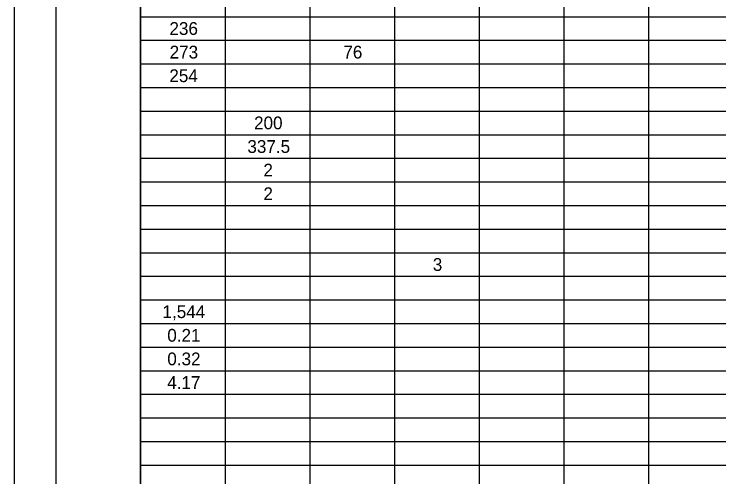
# Model space of a CAD drawing. Extents: x 0 to 34, y 0 to 22.
# Drawn here: x 0 to 8.36, y 11 to 16.49 of the extents above; entities that cross this region are included whole.
import ezdxf

# ---------------------------------------------------------------- set-up
doc = ezdxf.new("R2010")
doc.units = 0
for name, color, linetype in [('Default', 7, 'Continuous'), ('SH_Border', 7, 'Continuous'), ('SH_Cut_Line', 7, 'Continuous')]:
    doc.layers.add(name, color=color, linetype=linetype)

msp = doc.modelspace()

# ---------------------------------------------------------------- linework, layer by layer
at = {"layer": 'Default'}
for p, q in [((1.5, 21.5), (1.5, 0.5)), ((2.5046, 20.94), (2.5046, 0.5)), ((3.5092, 20.94), (3.5092, 0.5)), ((4.5138, 20.94), (4.5138, 0.5)), ((5.5184, 20.94), (5.5184, 0.5)), ((6.5229, 20.94), (6.5229, 0.5)), ((7.5275, 20.94), (7.5275, 0.5)), ((1.5, 16.46), (32, 16.46)), ((1.5, 16.18), (32, 16.18)), ((1.5, 15.9), (32, 15.9)), ((1.5, 15.62), (32, 15.62)), ((1.5, 15.34), (32, 15.34)), ((1.5, 15.06), (32, 15.06)), ((1.5, 14.78), (32, 14.78)), ((1.5, 14.5), (32, 14.5)), ((1.5, 14.22), (32, 14.22)), ((1.5, 13.94), (32, 13.94)), ((1.5, 13.66), (32, 13.66)), ((1.5, 13.38), (32, 13.38)), ((1.5, 13.1), (32, 13.1)), ((1.5, 12.82), (32, 12.82)), ((1.5, 12.54), (32, 12.54)), ((1.5, 12.26), (32, 12.26)), ((1.5, 11.98), (32, 11.98)), ((1.5, 11.7), (32, 11.7)), ((1.5, 11.42), (32, 11.42)), ((1.5, 11.14), (32, 11.14))]:
    msp.add_line(p, q, dxfattribs=at)
at = {"layer": 'SH_Border'}
for points in [[(0.5, 21.5), (1.5, 21.5), (1.5, 0.5), (0.5, 0.5)], [(1.5, 21.5), (33.5, 21.5), (33.5, 0.5), (1.5, 0.5)]]:
    msp.add_lwpolyline(points, close=True, dxfattribs=at)
at = {"layer": 'SH_Cut_Line'}
msp.add_lwpolyline([(0, 0), (34, 0), (34, 22), (0, 22)], close=True, dxfattribs=at)

# ---------------------------------------------------------------- texts
at = {"layer": 'Default'}
for s, height, p in [('236', 0.15153, (1.8433, 16.2442)), ('273', 0.15153, (1.8456, 15.9642)), ('76', 0.15153, (3.9069, 15.9642)), ('254', 0.15153, (1.8421, 15.6842)), ('200', 0.15153, (2.8473, 15.1242)), ('337.5', 0.15153, (2.7683, 14.8442)), ('2', 0.1515, (2.9584, 14.5642)), ('2', 0.1515, (2.9584, 14.2842)), ('3', 0.1515, (4.9682, 13.4442)), ('1,544', 0.15153, (1.7609, 12.8842)), ('0.21', 0.15153, (1.8177, 12.6042)), ('0.32', 0.15153, (1.8179, 12.3242)), ('4.17', 0.15153, (1.8168, 12.0442))]:
    msp.add_text(s, height=height, dxfattribs=at).set_placement(p)

doc.saveas('drawing.dxf')
